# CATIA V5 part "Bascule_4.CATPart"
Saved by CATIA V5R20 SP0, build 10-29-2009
Part number: Bascule_4
Publications: "Droite_CD", "Droite_DE", "Droite_CE", "Axe_pivot_bascule_4_point_C", "Axe_pivot_bascule_4_point_D", "Axe_pivot_bascule_4_point_E", "Plan_ref"
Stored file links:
  C:\Users\J\IAO_2012_jgossard\Bascule_4.CATPart
  C:\Users\J\IAO_2012_jgossard\squelette_mecanisme_presse.CATProduct

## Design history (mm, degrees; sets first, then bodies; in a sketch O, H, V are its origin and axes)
Set1
  Point1 "Point_C": linked copy from another document
  Point2 "Point_D": linked copy from another document
  Point3 "Point_E": linked copy from another document
  Plane1 "Plan_ref": linked copy from another document
Body1 (main body)
  Line1 "Droite_CD": type PtPt, FirstPoint Point1, SecondPoint Point2
  Line2 "Droite_DE": type PtPt, FirstPoint Point2, SecondPoint Point3
  Line3 "Droite_CE": type PtPt, FirstPoint Point1, SecondPoint Point3
  Line4 "Axe_pivot_bascule_4_point_C": type Normal, RefPoint Point1, RefSkin Plane1, Start 0, End 10
  Line5 "Axe_pivot_bascule_4_point_D": type Normal, RefPoint Point2, RefSkin Plane1, Start 0, End 10
  Line6 "Axe_pivot_bascule_4_point_E": type Normal, RefPoint Point3, RefSkin Plane1, Start 0, End 10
